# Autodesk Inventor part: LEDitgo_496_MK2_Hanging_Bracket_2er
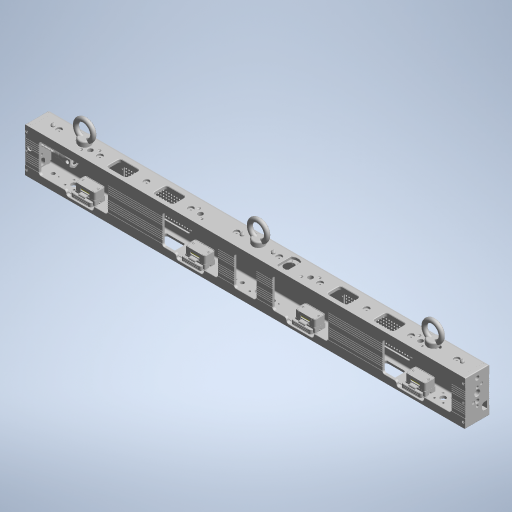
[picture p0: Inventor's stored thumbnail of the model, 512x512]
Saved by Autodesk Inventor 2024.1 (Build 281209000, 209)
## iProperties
Company: LEDitgo Videowall Germany GmbH
Created: 2024-11
Part Number: LEDitgo_496_MK2_Hanging_Bracket_2er
Material: Allgemein
Document SubType Name: Modellieren
Designer: Tobias Jandausch
Appearance: Vorgabe
Project: 496 MK2 Serie
Description: 496 MK2 Hanging Bracket 2er
Sending System: SIEMENS PLM Software NX 12.0
Preprocessor: ST-DEVELOPER v16.7
Title: LEDitgo_496_MK2_Hanging_Bracket_2er
Revision Number: 01
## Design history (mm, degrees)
feature "Basis1"
feature "KM3X22" [Basis]
feature "KM3X22:1" [Basis]
feature "KM3X22:2" [Basis]
feature "KM3X22:3" [Basis]
feature "Basis6"
feature "Basis7"
feature "Basis8"
feature "Basis9"
feature "Basis10"
feature "12X4-S" [Basis]
feature "12X4-S:1" [Basis]
feature "12X4-S:2" [Basis]
feature "12X4-S:3" [Basis]
feature "12X4-S:4" [Basis]
feature "KM3X22:4" [Basis]
feature "KM3X22:5" [Basis]
feature "KM3X22:6" [Basis]
feature "Basis19"
feature "KM3X22:7" [Basis]
feature "KM3X22:8" [Basis]
feature "KM3X22:9" [Basis]
feature "Basis23"
feature "KM3X22:10" [Basis]
feature "KM3X22:11" [Basis]
feature "KM3X22:12" [Basis]
feature "KM3X22:13" [Basis]
feature "Basis28"
feature "Basis29"
feature "PTM3.00-0.00" [Basis]
feature "Basis31"
feature "Basis32"
feature "Basis33"
feature "PTM3.00-0.00:1" [Basis]
feature "Basis35"
feature "Basis36"
feature "PTM3.00-0.00:2" [Basis]
feature "Basis38"
feature "PTM3.00-0.00:3" [Basis]
feature "Basis40"
feature "Basis41"
feature "KM3X22:14" [Basis]
feature "KM3X22:15" [Basis]
feature "Basis44"
feature "Basis45"
feature "Basis46"
feature "Basis47"
feature "Basis48"
feature "Basis49"
feature "Basis50"
feature "Basis51"
feature "Basis52"
feature "PTM3.00-0.00:4" [Basis]
feature "Basis54"
feature "KM3X22:16" [Basis]
feature "Basis56"
feature "PTM3.00-0.00:5" [Basis]
feature "KM3X22:17" [Basis]
feature "PTM3.00-0.00:6" [Basis]
feature "PTM3.00-0.00:7" [Basis]
feature "Basis61"
feature "Basis62"
feature "Basis63"
feature "XT-DWZ" [Basis]
feature "XT-DWZ:1" [Basis]
feature "Basis66"
feature "KM3X22:18" [Basis]
feature "Basis68"
feature "Basis69"
feature "PTM3.00-0.00:8" [Basis]
feature "Basis71"
feature "Basis72"
feature "Basis73"
feature "Basis74"
feature "Basis75"
feature "Basis76"
feature "Basis77"
feature "Basis78"
feature "XT-DWZ:2" [Basis]
feature "Basis80"
feature "Basis81"
feature "PTM3.00-0.00:9" [Basis]
feature "Basis83"
feature "Basis84"
feature "Basis85"
feature "Basis86"
feature "Basis87"
feature "KM3X22:19" [Basis]
feature "Basis89"
feature "KM3X22:20" [Basis]
feature "Basis91"
feature "PTM3.00-0.00:10" [Basis]
feature "PTM3.00-0.00:11" [Basis]
feature "Basis94"
feature "Basis95"
feature "Basis96"
feature "Basis97"
feature "KM3X22:21" [Basis]
feature "XT-DWZ:3" [Basis]
feature "KM3X22:22" [Basis]
feature "Basis101"
feature "Basis102"
feature "PTM3.00-0.00:12" [Basis]
feature "Basis104"
feature "Basis105"
feature "KM3X22:23" [Basis]
feature "KM3X22:24" [Basis]
feature "XT-DWZ:4" [Basis]
feature "PTM3.00-0.00:13" [Basis]
feature "Basis110"
feature "Basis111"
feature "KM3X22:25" [Basis]
feature "PTM3.00-0.00:14" [Basis]
feature "PTM3.00-0.00:15" [Basis]
feature "Basis115"
feature "KM3X22:26" [Basis]
feature "KM3X22:27" [Basis]
feature "Basis118"
feature "KM3X22:28" [Basis]
feature "Basis120"
feature "KM3X22:29" [Basis]
feature "KM3X22:30" [Basis]
feature "KM3X22:31" [Basis]
feature "PM4X10" [Basis]
feature "12X4-S:5" [Basis]
feature "12X4-S:6" [Basis]
feature "12X4-S:7" [Basis]
feature "12X4-S:8" [Basis]
feature "12X4-S:9" [Basis]
feature "Basis130"
feature "Basis131"
feature "KM3X22:32" [Basis]
feature "KM3X22:33" [Basis]
feature "KM3X22:34" [Basis]
feature "KM3X22:35" [Basis]
feature "KM3X22:36" [Basis]
feature "KM3X22:37" [Basis]
feature "KM3X22:38" [Basis]
feature "Basis139"
feature "KM3X22:39" [Basis]
feature "Basis141"
feature "Basis142"
feature "Basis143"
feature "Basis144"
feature "XT-DWZ:5" [Basis]
feature "Basis146"
feature "Basis147"
feature "Basis148"
feature "Basis149"
feature "Basis150"
node "Volumenkörper74"
node "Volumenkörper"
node "Flächenkörper"
node "Volumenkörper1"
node "Volumenkörper2"
node "Volumenkörper3"
node "Volumenkörper4"
node "Volumenkörper75"
node "Volumenkörper76"
node "Volumenkörper77"
node "Volumenkörper78"
node "Volumenkörper79"
node "Volumenkörper5"
node "Volumenkörper6"
node "Volumenkörper7"
node "Volumenkörper8"
node "Volumenkörper9"
node "Volumenkörper10"
node "Volumenkörper11"
node "Volumenkörper12"
node "Volumenkörper80"
node "Volumenkörper13"
node "Volumenkörper14"
node "Volumenkörper15"
node "Volumenkörper81"
node "Volumenkörper16"
node "Volumenkörper17"
node "Volumenkörper18"
node "Volumenkörper19"
node "Volumenkörper82"
node "Volumenkörper83"
node "Volumenkörper20"
node "Volumenkörper84"
node "Volumenkörper85"
node "Volumenkörper86"
node "Volumenkörper21"
node "Volumenkörper87"
node "Volumenkörper88"
node "Volumenkörper22"
node "Volumenkörper89"
node "Volumenkörper23"
node "Volumenkörper90"
node "Volumenkörper91"
node "Volumenkörper24"
node "Volumenkörper25"
node "Volumenkörper92"
node "Volumenkörper93"
node "Volumenkörper94"
node "Volumenkörper95"
node "Volumenkörper96"
node "Volumenkörper97"
node "Volumenkörper98"
node "Volumenkörper99"
node "Volumenkörper100"
node "Volumenkörper26"
node "Volumenkörper101"
node "Volumenkörper27"
node "Volumenkörper102"
node "Volumenkörper28"
node "Volumenkörper29"
node "Volumenkörper30"
node "Volumenkörper31"
node "Volumenkörper103"
node "Volumenkörper104"
node "Volumenkörper105"
node "Volumenkörper32"
node "Volumenkörper33"
node "Volumenkörper106"
node "Volumenkörper34"
node "Volumenkörper107"
node "Volumenkörper108"
node "Volumenkörper35"
node "Volumenkörper109"
node "Volumenkörper110"
node "Volumenkörper111"
node "Volumenkörper112"
node "Volumenkörper113"
node "Volumenkörper114"
node "Volumenkörper115"
node "Volumenkörper116"
node "Volumenkörper36"
node "Volumenkörper117"
node "Volumenkörper118"
node "Volumenkörper37"
node "Volumenkörper119"
node "Volumenkörper120"
node "Volumenkörper121"
node "Volumenkörper122"
node "Volumenkörper123"
node "Volumenkörper38"
node "Volumenkörper124"
node "Volumenkörper39"
node "Volumenkörper125"
node "Volumenkörper40"
node "Volumenkörper41"
node "Volumenkörper126"
node "Volumenkörper127"
node "Volumenkörper128"
node "Volumenkörper129"
node "Volumenkörper42"
node "Volumenkörper43"
node "Volumenkörper44"
node "Volumenkörper130"
node "Volumenkörper131"
node "Volumenkörper45"
node "Volumenkörper132"
node "Volumenkörper133"
node "Volumenkörper46"
node "Volumenkörper47"
node "Volumenkörper48"
node "Volumenkörper49"
node "Volumenkörper134"
node "Volumenkörper135"
node "Volumenkörper50"
node "Volumenkörper51"
node "Volumenkörper52"
node "Volumenkörper136"
node "Volumenkörper53"
node "Volumenkörper54"
node "Volumenkörper137"
node "Volumenkörper55"
node "Volumenkörper138"
node "Volumenkörper56"
node "Volumenkörper57"
node "Volumenkörper58"
node "Volumenkörper59"
node "Volumenkörper60"
node "Volumenkörper61"
node "Volumenkörper62"
node "Volumenkörper63"
node "Volumenkörper64"
node "Volumenkörper139"
node "Volumenkörper140"
node "Volumenkörper65"
node "Volumenkörper66"
node "Volumenkörper67"
node "Volumenkörper68"
node "Volumenkörper69"
node "Volumenkörper70"
node "Volumenkörper71"
node "Volumenkörper141"
node "Volumenkörper72"
node "Volumenkörper142"
node "Volumenkörper143"
node "Volumenkörper144"
node "Volumenkörper145"
node "Volumenkörper73"
node "Volumenkörper146"
node "Volumenkörper147"
node "Volumenkörper148"
node "Volumenkörper149"
node "Volumenkörper150"
